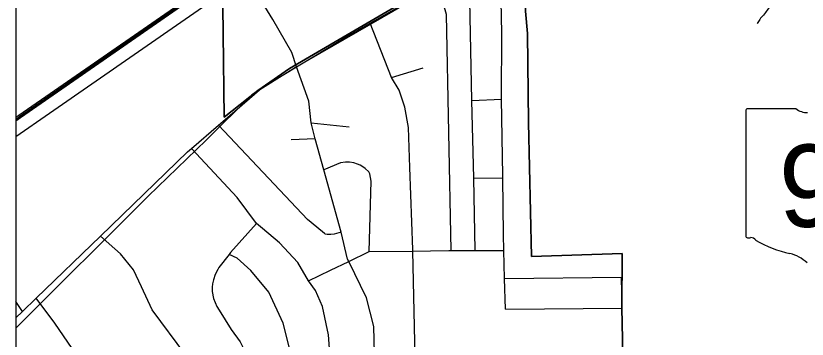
# Model space of a CAD drawing. Extents: x 0 to 44.3, y 0 to 22.
# Drawn here: x 2.1 to 3.367, y 16.349 to 16.867 of the extents above; entities that cross this region are included whole.
import ezdxf

# ---------------------------------------------------------------- set-up
doc = ezdxf.new("R2010")
doc.units = 0
for name, color, linetype in [('GM_X_City_Street', 7, 'Continuous'), ('GM_X_Corporation', 7, 'Continuous'), ('GM_X_County_Road', 7, 'Continuous'), ('GM_X_Minor_River', 7, 'Continuous'), ('GM_X_Rail_Line', 7, 'Continuous'), ('GM_X_State_Location', 7, 'Continuous'), ('GM_X_State_Shield', 7, 'Continuous'), ('GM_X_US_Route', 7, 'Continuous')]:
    doc.layers.add(name, color=color, linetype=linetype)

msp = doc.modelspace()

# ---------------------------------------------------------------- linework, layer by layer
at = {"layer": 'GM_X_City_Street'}
for p, q in [((2.7011, 16.7688), (2.7518, 16.7842)), ((2.8301, 16.7319), (2.8775, 16.7336)), ((2.5726, 16.696), (2.6336, 16.6896)), ((2.5791, 16.6705), (2.5407, 16.6688)), ((2.8328, 16.607), (2.8797, 16.6076)), ((2.8823, 16.4464), (3.0693, 16.4486)), ((3.0704, 16.3988), (3.0693, 16.4486)), ((2.1109, 16.3937), (2.1, 16.4095)), ((2.8838, 16.397), (3.0704, 16.3988))]:
    msp.add_line(p, q, dxfattribs=at)
for points in [[(2.8838, 16.397), (2.8823, 16.4464), (2.8812, 16.4912), (2.8808, 16.5172), (2.8797, 16.6076), (2.8797, 16.6113), (2.8775, 16.7336), (2.8775, 16.7347), (2.8781, 16.8395), (2.8767, 16.8915), (2.8727, 16.9264), (2.8667, 16.9411), (2.8568, 16.964)], [(2.8354, 16.4912), (2.8328, 16.607), (2.8301, 16.7319), (2.8267, 16.8924), (2.826, 16.8974), (2.8231, 16.9044), (2.819, 16.9136), (2.8053, 16.9347)], [(2.7967, 16.4911), (2.7892, 16.8693), (2.7873, 16.8768), (2.7844, 16.8852), (2.7823, 16.89), (2.7666, 16.9126)], [(2.7035, 16.0985), (2.7205, 16.1101), (2.7272, 16.1161), (2.7324, 16.1229), (2.7353, 16.1308), (2.7394, 16.144), (2.7405, 16.1526), (2.739, 16.303), (2.7389, 16.3208), (2.7356, 16.4904), (2.7356, 16.4927), (2.7308, 16.6244), (2.7285, 16.6885), (2.7226, 16.721), (2.7133, 16.7482), (2.7011, 16.7688), (2.6673, 16.8558)], [(2.6207, 16.5206), (2.6095, 16.5174), (2.604, 16.5169), (2.5983, 16.5171), (2.5959, 16.5175), (2.5948, 16.5178), (2.5939, 16.5184), (2.5909, 16.521), (2.567, 16.541), (2.4242, 16.692)], [(2.6201, 16.0808), (2.6165, 16.1122), (2.6097, 16.2529), (2.603, 16.3254), (2.6028, 16.3265), (2.6005, 16.356), (2.5909, 16.4014), (2.5794, 16.427), (2.5684, 16.4427), (2.5513, 16.472), (2.5222, 16.5037), (2.4947, 16.5267), (2.4853, 16.5347), (2.4541, 16.576), (2.381, 16.6548)], [(2.6657, 16.4895), (2.669, 16.6023), (2.6667, 16.6141), (2.665, 16.6174), (2.659, 16.6229), (2.6553, 16.6255), (2.6511, 16.6279), (2.6467, 16.6299), (2.6408, 16.6317), (2.6343, 16.6328), (2.6277, 16.6328), (2.6199, 16.6317), (2.5929, 16.6208)], [(2.4853, 16.5347), (2.4438, 16.4879), (2.4414, 16.4848), (2.4251, 16.4638), (2.4233, 16.4611), (2.4192, 16.453), (2.4163, 16.4445), (2.4146, 16.4377), (2.4144, 16.4323), (2.4144, 16.4256), (2.4163, 16.4146), (2.4218, 16.4017), (2.4253, 16.3954), (2.4444, 16.3647), (2.4592, 16.3448), (2.4626, 16.3373), (2.4701, 16.3143), (2.4729, 16.3), (2.4797, 16.2667), (2.4861, 16.1692), (2.4909, 16.0968), (2.4919, 16.0593)], [(2.4176, 16.1275), (2.4154, 16.1503), (2.4152, 16.1522), (2.4109, 16.2077), (2.4107, 16.2417), (2.4097, 16.252), (2.4073, 16.2614), (2.3912, 16.284), (2.3904, 16.2858), (2.372, 16.3237), (2.3183, 16.3963), (2.3013, 16.4332), (2.2886, 16.4603), (2.2677, 16.4861), (2.2353, 16.5143)], [(2.5684, 16.4427), (2.6038, 16.4597), (2.6329, 16.4737), (2.6657, 16.4895), (2.7356, 16.4904), (2.7635, 16.4907), (2.7929, 16.4911), (2.7967, 16.4911), (2.8321, 16.4912), (2.8354, 16.4912), (2.8812, 16.4912)], [(2.5528, 16.0712), (2.5445, 16.1487), (2.5479, 16.2096), (2.5439, 16.2808), (2.5414, 16.3133), (2.5404, 16.326), (2.5281, 16.3747), (2.5051, 16.4247), (2.4764, 16.4595), (2.4544, 16.4792), (2.4414, 16.4848)], [(2.2655, 15.8683), (2.245, 16.1043), (2.2409, 16.1466), (2.2407, 16.1488), (2.2371, 16.2036), (2.237, 16.206), (2.2351, 16.2417), (2.229, 16.2651), (2.219, 16.2899), (2.2038, 16.3139), (2.1624, 16.3746), (2.1326, 16.4148)]]:
    msp.add_lwpolyline(points, dxfattribs=at)
at = {"layer": 'GM_X_Corporation'}
for points in [[(2.6435, 19.7561), (2.6112, 19.7153), (2.5841, 19.6689), (2.5328, 19.6017), (2.497, 19.5557), (2.4485, 19.5015), (2.3525, 19.3694), (2.3224, 19.3237), (2.3158, 19.3082), (2.3077, 19.2946), (2.2927, 19.2788), (2.2754, 19.2607), (2.2653, 19.2426), (2.2598, 19.2263), (2.2513, 19.21), (2.2332, 19.1893), (2.2255, 19.1757), (2.2227, 19.1685), (2.2142, 19.1541), (2.1876, 19.1149), (2.1582, 19.068), (2.1, 18.9995), (2.1, 14.1)], [(2.6435, 19.7561), (2.6112, 19.7153), (2.5841, 19.6689), (2.5328, 19.6017), (2.497, 19.5557), (2.4485, 19.5015), (2.3525, 19.3694), (2.3224, 19.3237), (2.3158, 19.3082), (2.3077, 19.2946), (2.2927, 19.2788), (2.2754, 19.2607), (2.2653, 19.2426), (2.2598, 19.2263), (2.2513, 19.21), (2.2332, 19.1893), (2.2255, 19.1757), (2.2227, 19.1685), (2.2142, 19.1541), (2.1876, 19.1149), (2.1582, 19.068), (2.1, 18.9995), (2.1, 14.1)], [(3.8489, 17.8842), (3.4718, 17.6223), (2.8541, 17.1959), (2.7194, 17.1037), (2.7996, 16.9364), (2.8787, 16.9814), (2.9148, 16.9035), (2.9156, 16.875), (2.9192, 16.8391), (2.9204, 16.6966), (2.9251, 16.4817), (3.0704, 16.4866), (3.0702, 16.3994), (3.0821, 15.82), (3.1447, 15.8221), (3.1444, 15.7503), (3.6077, 15.7576), (3.6013, 15.9867), (3.6481, 15.9878), (3.6443, 16.103), (3.9637, 16.1137), (4.243, 16.3316)]]:
    msp.add_lwpolyline(points, dxfattribs=at)
for points in [[(2.1, 19.0236), (2.1, 17.1027), (2.4288, 17.1065), (2.4335, 16.7048), (2.4871, 16.7475), (2.538, 16.7829), (2.7996, 16.9364), (2.7194, 17.1037), (2.6942, 17.1562), (2.6288, 17.5345), (2.622, 17.8601), (2.5913, 17.8593), (2.5903, 17.9801), (2.61, 17.9818), (2.6089, 18.2161), (2.5941, 18.2156), (2.5965, 18.3102), (2.5949, 18.4003), (2.6952, 18.3996), (2.6915, 18.6022), (2.1784, 19.1187), (2.1485, 19.0743)], [(2.1, 17.1027), (2.1, 14.8909), (2.1501, 14.8903), (2.1516, 14.7764), (2.4165, 14.7887), (2.4154, 14.8107), (2.4119, 15.2288), (3.148, 15.2535), (3.1444, 15.7503), (3.1447, 15.8221), (3.0821, 15.82), (3.0702, 16.3994), (3.0704, 16.4866), (2.9251, 16.4817), (2.9204, 16.6966), (2.9192, 16.8391), (2.9156, 16.875), (2.9148, 16.9035), (2.8787, 16.9814), (2.7996, 16.9364), (2.538, 16.7829), (2.4871, 16.7475), (2.4335, 16.7048), (2.4288, 17.1065)]]:
    msp.add_lwpolyline(points, close=True, dxfattribs=at)
at = {"layer": 'GM_X_County_Road'}
for points in [[(2.5494, 16.7857), (2.542, 16.8085), (2.5111, 16.8614), (2.4431, 16.973)], [(2.7294, 15.8699), (2.7237, 15.9283), (2.7223, 15.9996), (2.7209, 16.0655), (2.7035, 16.0985), (2.691, 16.1234), (2.679, 16.1576), (2.6772, 16.1963), (2.6732, 16.3696), (2.661, 16.4156), (2.6329, 16.4737), (2.6311, 16.4776), (2.6207, 16.5206), (2.5929, 16.6208), (2.5791, 16.6705), (2.5726, 16.696), (2.5688, 16.7305), (2.5494, 16.7857)]]:
    msp.add_lwpolyline(points, dxfattribs=at)
at = {"layer": 'GM_X_Minor_River'}
msp.add_lwpolyline([(3.3439, 16.9252), (3.341, 16.9221), (3.338, 16.919), (3.3346, 16.9155), (3.332, 16.9132), (3.3298, 16.9109), (3.3279, 16.9082), (3.3257, 16.9055), (3.3228, 16.9012), (3.3187, 16.8966), (3.3149, 16.8935), (3.3123, 16.8904), (3.3101, 16.887), (3.3072, 16.8831), (3.3038, 16.8781), (3.3001, 16.8727), (3.2968, 16.8685), (3.2938, 16.8658), (3.292, 16.8635), (3.2909, 16.8615), (3.2886, 16.8585), (3.2864, 16.8554), (3.2864, 16.8554), (3.2864, 16.855)], dxfattribs=at)
at = {"layer": 'GM_X_Rail_Line'}
for points in [[(5.0399, 18.1234), (4.8858, 17.826), (4.8521, 17.786), (4.6557, 17.5832), (4.6326, 17.5692), (3.8528, 17.3319), (3.3907, 17.1879), (3.1392, 17.1176), (3.0576, 17.079), (2.5475, 16.7844), (2.4777, 16.7406), (2.4046, 16.6684), (2.3118, 16.5782), (2.1, 16.3666)], [(2.1, 16.6739), (2.1539, 16.7114), (2.7235, 17.1075), (3.4981, 17.6468), (4.1115, 18.074)], [(2.1, 16.7049), (2.1048, 16.7082), (2.3747, 16.896), (2.5221, 16.9973), (2.7533, 17.1586), (2.9361, 17.286), (3.5315, 17.7008), (3.6785, 17.8033)], [(2.1, 16.702), (2.1061, 16.7063), (2.3761, 16.894), (2.5234, 16.9954), (2.7546, 17.1567), (2.9374, 17.2841), (3.5329, 17.6989), (3.6799, 17.8014)], [(2.1, 16.6992), (2.1074, 16.7044), (2.3774, 16.8921), (2.5248, 16.9934), (2.756, 17.1548), (2.9388, 17.2822), (3.5342, 17.697), (3.6813, 17.7995)]]:
    msp.add_lwpolyline(points, dxfattribs=at)
at = {"layer": 'GM_X_State_Shield'}
for p, q in [((3.2685, 16.7152), (3.2685, 16.5151)), ((3.3483, 16.7186), (3.271, 16.7186))]:
    msp.add_line(p, q, dxfattribs=at)
for centre, radius, start, end in [((3.2715, 16.7156), 0.00305, 98.1301, 188.1301), ((3.3667, 16.7419), 0.0296, 231.6195, 271.1119), ((3.2715, 16.5146), 0.00308, 171.9584, 258.3066), ((3.272, 16.5351), 0.0235, 267.339, 280.6039), ((3.2768, 16.5035), 0.00848, 29.7484, 93.2717), ((3.3838, 16.6833), 0.2019, 240.4129, 257.1985), ((3.3236, 16.4252), 0.0632, 47.1842, 75.836)]:
    msp.add_arc(centre, radius, start, end, dxfattribs=at)
at = {"layer": 'GM_X_US_Route'}
for points in [[(2.4541, 16.7178), (2.4936, 16.7519), (2.5494, 16.7857), (2.628, 16.8334), (2.6673, 16.8558), (2.7666, 16.9126), (2.8053, 16.9347), (2.8073, 16.9358), (2.8141, 16.9397)], [(2.1, 16.3832), (2.1109, 16.3937), (2.1326, 16.4148), (2.2353, 16.5143), (2.3746, 16.6492), (2.381, 16.6548), (2.4242, 16.692), (2.4541, 16.7178)]]:
    msp.add_lwpolyline(points, dxfattribs=at)

# ---------------------------------------------------------------- texts
at = {"layer": 'GM_X_State_Location'}
msp.add_text('91', height=0.000189, rotation=0, dxfattribs=at).set_placement((3.3496, 16.588))
at = {"layer": 'GM_X_State_Shield'}
msp.add_text('91', height=0.13184, dxfattribs=at).set_placement((3.3212, 16.5292))

doc.saveas('drawing.dxf')
